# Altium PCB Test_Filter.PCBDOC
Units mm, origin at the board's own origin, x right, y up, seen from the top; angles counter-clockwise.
Board outline 162 x 102 mm, 2 copper layers (Top Layer, Bottom Layer), stack 1.53 mm thick; 25 components, 36 nets, 90 pads, 0 vias.
Unrouted connection lines stored in the file: 34.
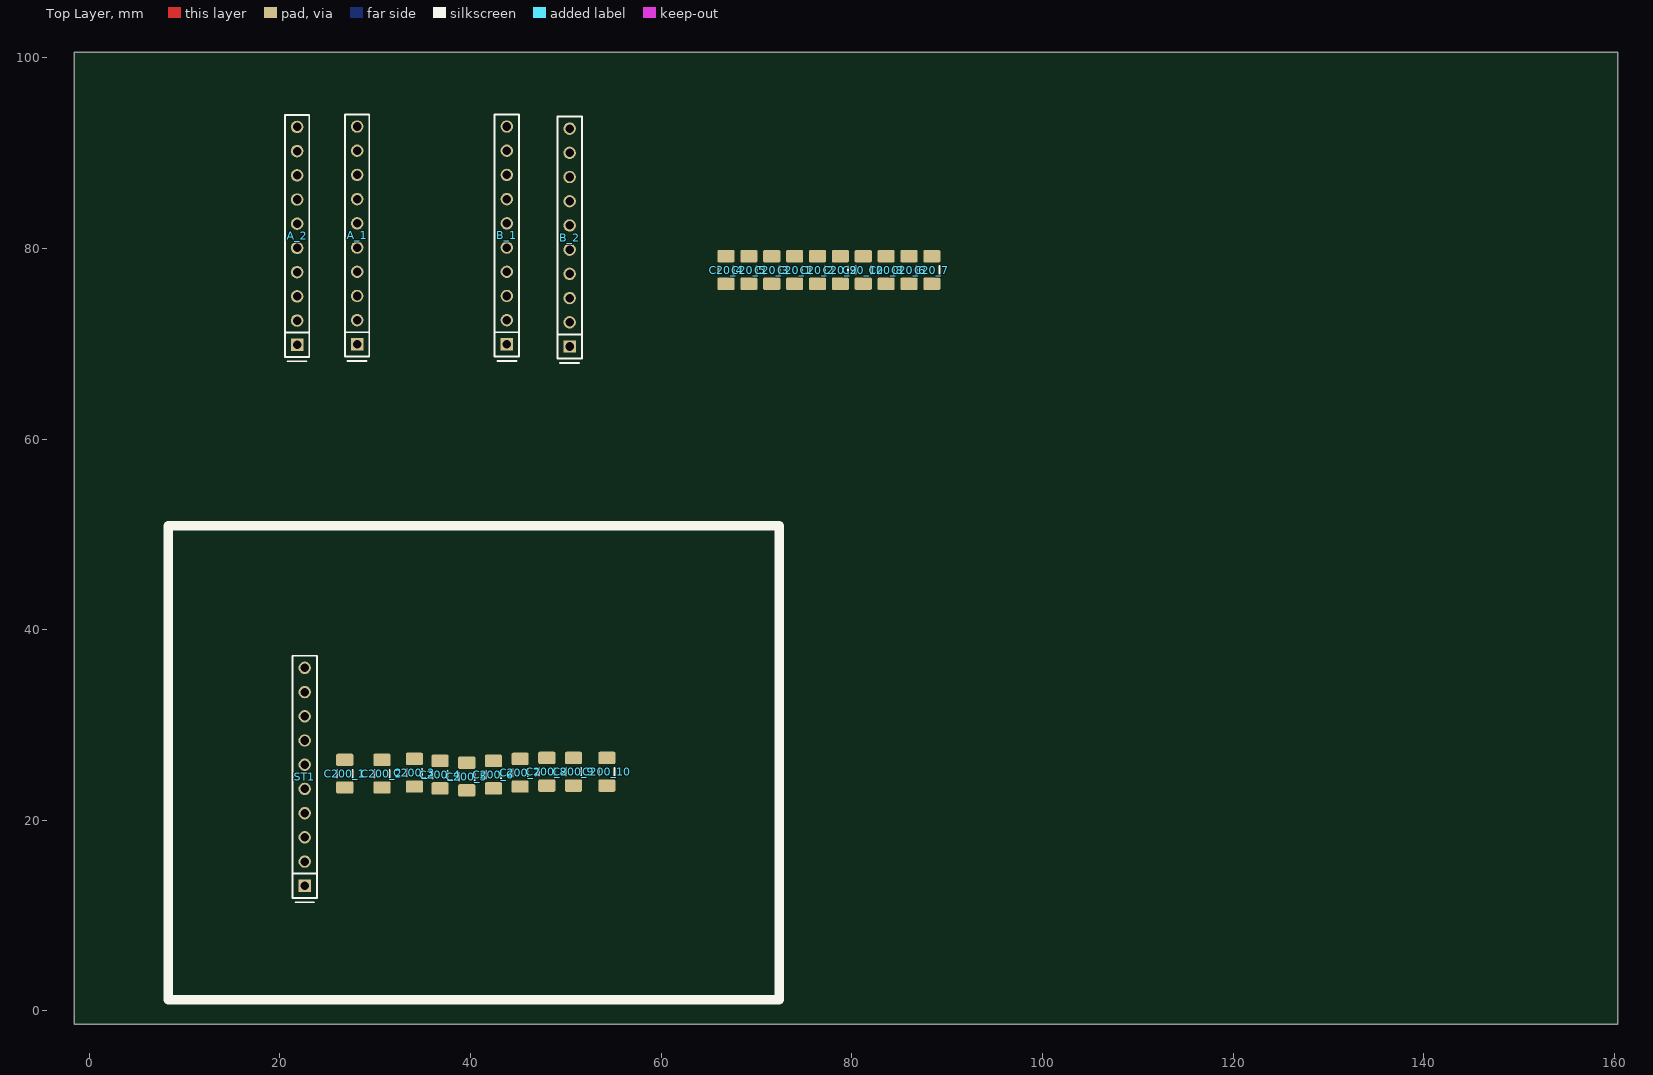
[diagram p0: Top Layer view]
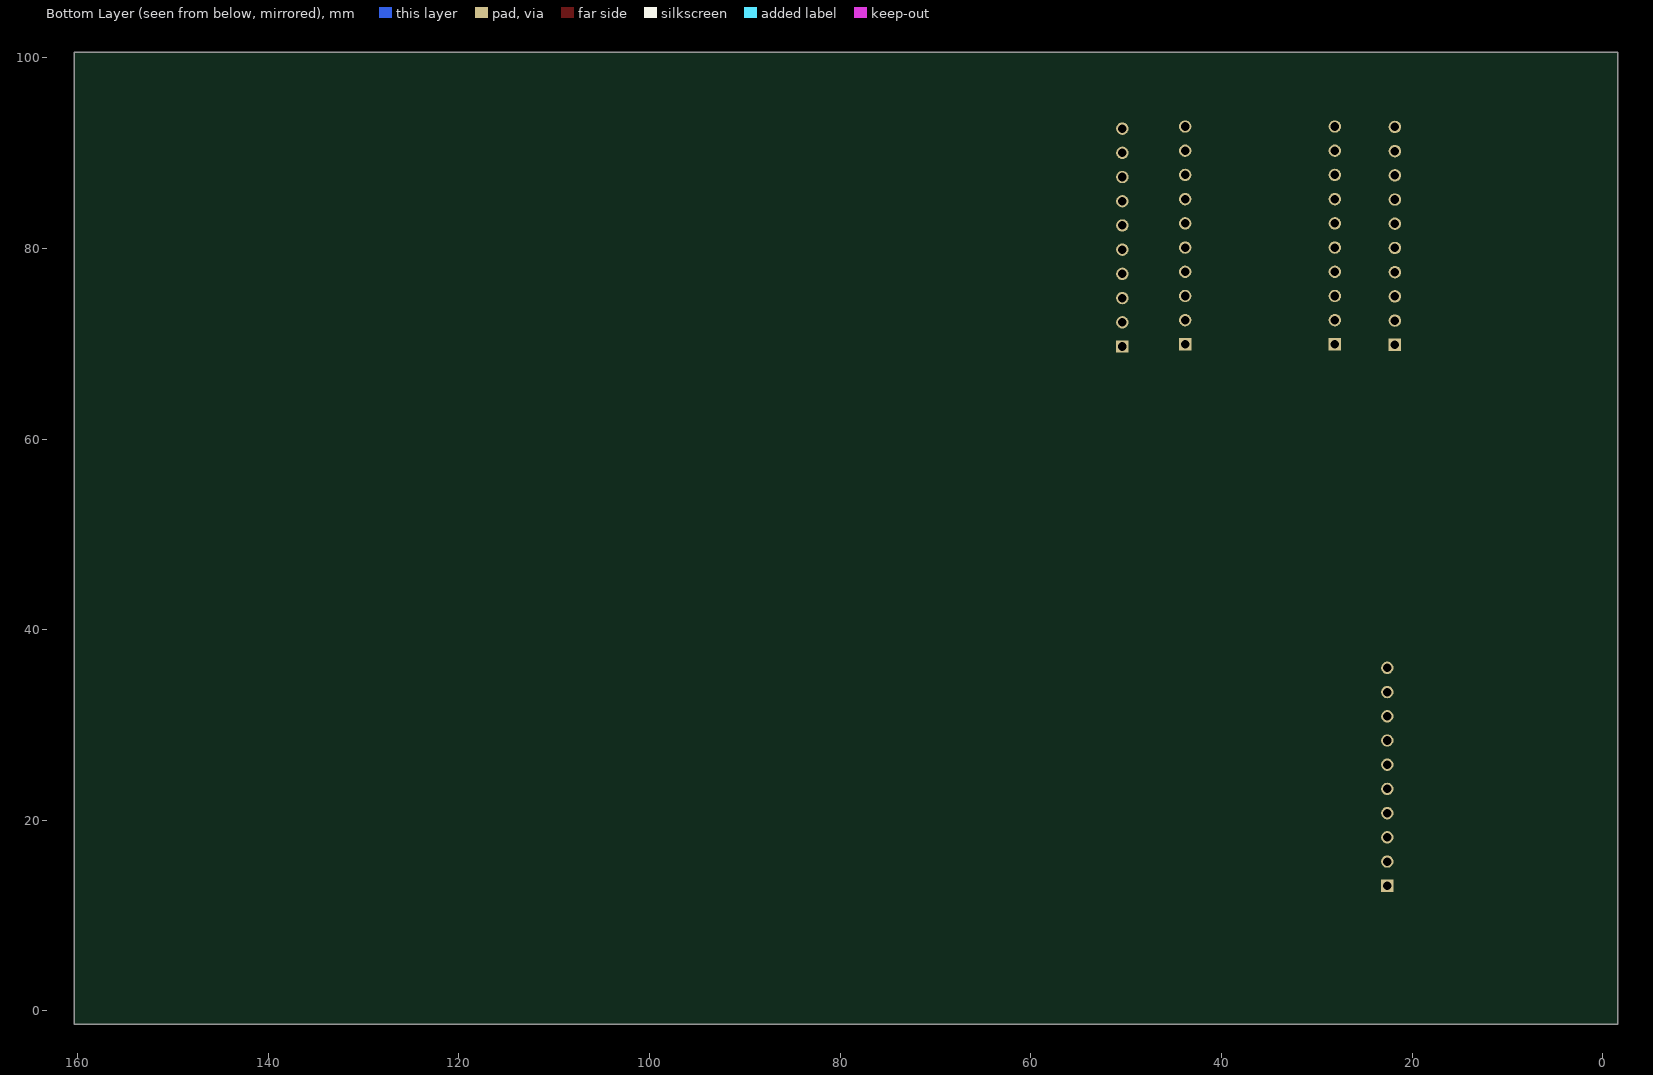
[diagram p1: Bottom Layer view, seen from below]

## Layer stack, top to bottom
Top Solder: solder mask 0.01, Solder Resist, Dk 3.5
Top Layer: signal copper 0.035
Dielectric1: core 1.46, FR-4, Dk 4.8
Bottom Layer: signal copper 0.035
Bottom Solder: solder mask 0.01, Solder Resist, Dk 3.5

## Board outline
-1.61,-1.381 -1.61,100.619 160.39,100.619 160.39,-1.381

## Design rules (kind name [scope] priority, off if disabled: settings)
Clearance Clearance_Fiducial [All vs HasFootprint('MISC_Fiducial_1mm')] p1: gap=0.5 ignorepadtopadclearanceinfootprint=FALSE except(0: Arc-Hole Track-Hole SMDPad-Hole THPad-Hole Via-Hole Fill-Hole Poly-Hole Region-Hole Text-Hole)
Clearance "Clearance_Polygon to Text" [IsText AND OnSignal vs InPolygon] p2: gap=-0.1 ignorepadtopadclearanceinfootprint=FALSE except(0: Arc-Hole Track-Hole SMDPad-Hole THPad-Hole Via-Hole Fill-Hole Poly-Hole Region-Hole Text-Hole)
Clearance Clearance_GND_Keepout [InNet('GND') vs OnLayer('Keep-Out Layer')] p3: gap=0.5 ignorepadtopadclearanceinfootprint=FALSE except(0: Arc-Hole Track-Hole SMDPad-Hole THPad-Hole Via-Hole Fill-Hole Poly-Hole Region-Hole Text-Hole) // GND nach Keepout
Clearance Clearance_GND_PolygonPlane [(InPolygon AND InNet('GND'))] p4: gap=0.3 ignorepadtopadclearanceinfootprint=FALSE except(0: Arc-Hole Track-Hole SMDPad-Hole THPad-Hole Via-Hole Fill-Hole Poly-Hole Region-Hole Text-Hole)
Clearance "Clearance ADUC841 Pads" [HasFootprint('TQFP65P1400X1400-52N')] p5: gap=0.25 ignorepadtopadclearanceinfootprint=FALSE except(0: Arc-Hole Track-Hole SMDPad-Hole THPad-Hole Via-Hole Fill-Hole Poly-Hole Region-Hole Text-Hole) // ADUC_Pads
Clearance "Clearance ADUC7026 Pads" [HasFootprint('TQFP50P1400X1400-80N')] p6: gap=0.2 ignorepadtopadclearanceinfootprint=FALSE except(0: Arc-Hole Track-Hole SMDPad-Hole THPad-Hole Via-Hole Fill-Hole Poly-Hole Region-Hole Text-Hole) // ADUC_Pads
Clearance [All] p7: gap=0.25 ignorepadtopadclearanceinfootprint=FALSE except(0: Arc-Hole Track-Hole SMDPad-Hole THPad-Hole Via-Hole Fill-Hole Poly-Hole Region-Hole Text-Hole)
ComponentClearance [All] p1: gap=0.25 collisioncheckmode=3 verticalgap=0.25 showdistances=FALSE
DiffPairsRouting [All] p1: maxlimit=0.25 minlimit=0.25 mostfreqgap=0.25 toplayer_minwidth=0.381 toplayer_maxwidth=0.381 toplayer_prefwidth=0.381 bottomlayer_minwidth=0.381 bottomlayer_maxwidth=0.381 bottomlayer_prefwidth=0.381 maxuncoupledlength=10
FabricationTestPointUsage TestPointUsage [All] p1: valid=0 allowmultiple=FALSE
FabricationTestpoint Testpoint [All] p1: side=3 testpointundercomponent=TRUE minsize=1.016 maxsize=2.54 preferedsize=1.524 minholesize=0 maxholesize=1.016 preferedholesize=0.813 testpointgrid=0.025 allowsidetop=TRUE allowsidebottom=TRUE usegrid=TRUE gridtolerance=0
Height [All] p1: minheight=0 maxheight=60 prefheight=12
HoleSize [All] p1: absolutevalues=TRUE maxlimit=20 minlimit=0.3 maxpercent=80.000 minpercent=20.000
HoleToHoleClearance [All] p1: gap=0.3 allowstackedmicrovias=TRUE
MinimumAnnularRing [All] p1: minimumring=0.2
MinimumSolderMaskSliver [All] p1: minsoldermaskwidth=0.1
NetAntennae [All] p1: netantennaetolerance=0.5
PlaneClearance [All] p1: clearance=0.25
PlaneConnect [All] p1: planeconnectstyle=Relief reliefexpansion=0.5 reliefentries=4 reliefconductorwidth=0.25 reliefairgap=0.25
PolygonConnect PolygonConnect_VIA [isvia] p1: connectstyle=Direct reliefconductorwidth=0.254 reliefentries=4 polygonreliefangle="90 Angle" airgapwidth=0.254
PolygonConnect [All] p2: connectstyle=Relief reliefconductorwidth=0.3 reliefentries=4 polygonreliefangle="90 Angle" airgapwidth=0.25
RoutingCorners [All] p1: cornerstyle=45-Degree minsetback=2 maxsetback=10
RoutingVias [All] p1: holewidth=0.4 width=0.8 viastyle="Through Hole" minholewidth=0.3 minwidth=0.6 maxholewidth=3 maxwidth=6
ShortCircuit "ShortCircuit_Polygon to Text" [IsText vs InPolygon] p1: allowed=TRUE
ShortCircuit [All] p2: allowed=FALSE
SilkToSilkClearance [All] p1: silktosilkclearance=0
SilkToSolderMaskClearance SilkscreenOverComponentPads [IsPad] p1: minsilkscreentomaskgap=0.15 clearancetoexposedcopper=TRUE
SolderMaskExpansion [All] p1: expansion=0.05 istentingtop=FALSE
Width Width_Trackends [All] p1: maxlimit=10 minlimit=0.25 preferedwidth=0.3 checkconnectedcopper=TRUE
Width [All] p2: maxlimit=10 minlimit=0.25 preferedwidth=0.3
15 further rules are at their usual default settings.

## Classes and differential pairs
net class In[2..10]: In2 In3 In4 In5 In6 In7 In8 In9 In10
channel class Sheet1: U_Sheet1 U_Sheet2
component class U_Sheet2: A_2 B_2
component class U_Sheet1: A_1 B_1
net class Cap[1..10]: Cap1 Cap2 Cap3 Cap4 Cap5 Cap6 Cap7 Cap8 Cap9 Cap10
component class UCap10: C20_10 C200_10
component class UCap9: C20_9 C200_9
component class UCap8: C20_8 C200_8
component class UCap7: C20_7 C200_7
component class UCap6: C20_6 C200_6
component class UCap5: C20_5 C200_5
component class UCap4: C20_4 C200_4
component class UCap3: C20_3 C200_3
component class UCap2: C20_2 C200_2
component class UCap1: C20_1 C200_1
component class Master_Sheet: ST1
channel class SubSheet_Cap: UCap1 UCap2 UCap3 UCap4 UCap5 UCap6 UCap7 UCap8 UCap9 UCap10

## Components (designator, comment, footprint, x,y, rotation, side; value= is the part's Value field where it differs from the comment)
A_1 "" CON_HDR1X10 28.1,81.37 r90 top (schematic designator A)
A_2 "" CON_HDR1X10 21.8,81.33 r90 top (schematic designator A)
B_1 "" CON_HDR1X10 43.8,81.37 r90 top (schematic designator B)
B_2 "" CON_HDR1X10 50.4,81.15 r90 top (schematic designator B)
C20_1 "100nF" CAPC3216X140N 74,77.746 r90 top (schematic designator C20)
C20_2 "100nF" CAPC3216X140N 76.4,77.746 r90 top (schematic designator C20)
C20_3 "100nF" CAPC3216X140N 71.6,77.746 r90 top (schematic designator C20)
C20_4 "100nF" CAPC3216X140N 66.8,77.746 r90 top (schematic designator C20)
C20_5 "100nF" CAPC3216X140N 69.2,77.746 r90 top (schematic designator C20)
C20_6 "100nF" CAPC3216X140N 86,77.746 r90 top (schematic designator C20)
C20_7 "100nF" CAPC3216X140N 88.4,77.746 r90 top (schematic designator C20)
C20_8 "100nF" CAPC3216X140N 83.6,77.746 r90 top (schematic designator C20)
C20_9 "100nF" CAPC3216X140N 78.8,77.746 r90 top (schematic designator C20)
C20_10 "100nF" CAPC3216X140N 81.2,77.746 r90 top (schematic designator C20)
C200_1 "100nF" CAPC3216X140N 26.8,24.9 r90 top (schematic designator C200)
C200_2 "100nF" CAPC3216X140N 30.7,24.9 r90 top (schematic designator C200)
C200_3 "100nF" CAPC3216X140N 34.1,25 r90 top (schematic designator C200)
C200_4 "100nF" CAPC3216X140N 36.8,24.8 r90 top (schematic designator C200)
C200_5 "100nF" CAPC3216X140N 39.6,24.6 r90 top (schematic designator C200)
C200_6 "100nF" CAPC3216X140N 42.4,24.8 r90 top (schematic designator C200)
C200_7 "100nF" CAPC3216X140N 45.2,25 r90 top (schematic designator C200)
C200_8 "100nF" CAPC3216X140N 48,25.1 r90 top (schematic designator C200)
C200_9 "100nF" CAPC3216X140N 50.8,25.1 r90 top (schematic designator C200)
C200_10 "100nF" CAPC3216X140N 54.3,25.1 r90 top (schematic designator C200)
ST1 "" CON_HDR1X10 22.6,24.57 r90 top

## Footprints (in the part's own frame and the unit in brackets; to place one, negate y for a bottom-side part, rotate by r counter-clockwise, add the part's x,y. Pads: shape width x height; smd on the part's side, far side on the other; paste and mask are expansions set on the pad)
CAPC3216X140N [mm] "Chip Capacitor, Body 3.2x1.6mm, IPC Medium Density"
  rrect25% 1.3x1.8 smd: 1(-1.45,0) 2(1.45,0)
  silkscreen extent -0.4,-0.8 0.4,0.8, body extent -1.6,-0.8 1.6,0.8, height 1
CON_HDR1X10 [mm] "Header; 10 Leads; Body 2.54 x 25.4 x 8.6 mm (typ); Pitch 2.54 mm"
  rect 1.3x1.3 hole 0.9: 1(-11.43,0)
  round 1.3 hole 0.9: 2(-8.89,0) 3(-6.35,0) 4(-3.81,0) 5(-1.27,0) 6(1.27,0) 7(3.81,0) 8(6.35,0) 9(8.89,0) 10(11.43,0)
  silkscreen extent -13.16,-1.27 12.7,1.27, body extent -12.7,-1.27 12.7,1.27, height 8.6

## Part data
A_1 A_2 B_1 B_2 ST1: library part "CON_Header 10", "Header, 10-Pin", Mfr Part Number="Samtec TSW-110-07-L-S", Supplier Part Number 1=SAM1031-10-ND
C20_1 C20_2 C20_3 C20_4 C20_5 C20_6 C20_7 C20_8 C20_9 C20_10 C200_1 C200_2 C200_3 C200_4 C200_5 C200_6 C200_7 C200_8 C200_9 C200_10: library part CAP_Chip_3216, "Capacitor General", Mfr Part Number="e.g. Vishay VJ1210Y104KXCT (100nF)"

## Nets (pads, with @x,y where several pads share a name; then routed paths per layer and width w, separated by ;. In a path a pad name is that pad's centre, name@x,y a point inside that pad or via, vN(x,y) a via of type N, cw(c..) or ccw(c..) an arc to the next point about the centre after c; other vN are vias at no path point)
Cap1: A_1.1 C20_1.1
Cap2: A_1.2 C20_2.1
Cap3: A_1.3 C20_3.1
Cap4: A_1.4 C20_4.1
Cap5: A_1.5 C20_5.1
Cap6: A_1.6 C20_6.1
Cap7: A_1.7 C20_7.1
Cap8: A_1.8 C20_8.1
Cap9: A_1.9 C20_9.1
Cap10: A_1.10 C20_10.1
GND: B_2.1 C20_1.2 C20_2.2 C20_3.2 C20_4.2 C20_5.2 C20_6.2 C20_7.2 C20_8.2 C20_9.2 C20_10.2
HAR.DC1_2: A_2.1
HAR.DC2_2: A_2.2
HAR.DC3_2: A_2.3
HAR.DC4_2: A_2.4
HAR.DC5_2: A_2.5
HAR.DC6_2: A_2.6
HAR.DC7_2: A_2.7
HAR.DC8_2: A_2.8
HAR.DC9_2: A_2.9
HAR.DC10_2: A_2.10
In1: C200_1.1 ST1.1
In2: C200_1.2 C200_2.1
In3: C200_2.2 C200_3.1
In4: C200_3.2 C200_4.1
In5: C200_4.2 C200_5.1
In6: C200_5.2 C200_6.1
In7: C200_6.2 C200_7.1
In8: C200_7.2 C200_8.1
In9: C200_8.2 C200_9.1
In10: C200_9.2 C200_10.1
NetB_1_1: B_1.1
Out10: C200_10.2 ST1.10
Test.T1: B_1.8 B_2.8
Test.T2: B_1.9 B_2.9
Test.T3: B_1.10 B_2.10
pads on no net: B_1.2 B_1.3 B_1.4 B_1.5 B_1.6 B_1.7 B_2.2 B_2.3 B_2.4 B_2.5 B_2.6 B_2.7 ST1.2 ST1.3 ST1.4 ST1.5 ST1.6 ST1.7 ST1.8 ST1.9

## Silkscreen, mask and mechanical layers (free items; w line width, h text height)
Top Overlay:
  lines w1: 8.3,1.2 72.4,1.2 72.4,50.9 8.3,50.9 8.3,1.2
